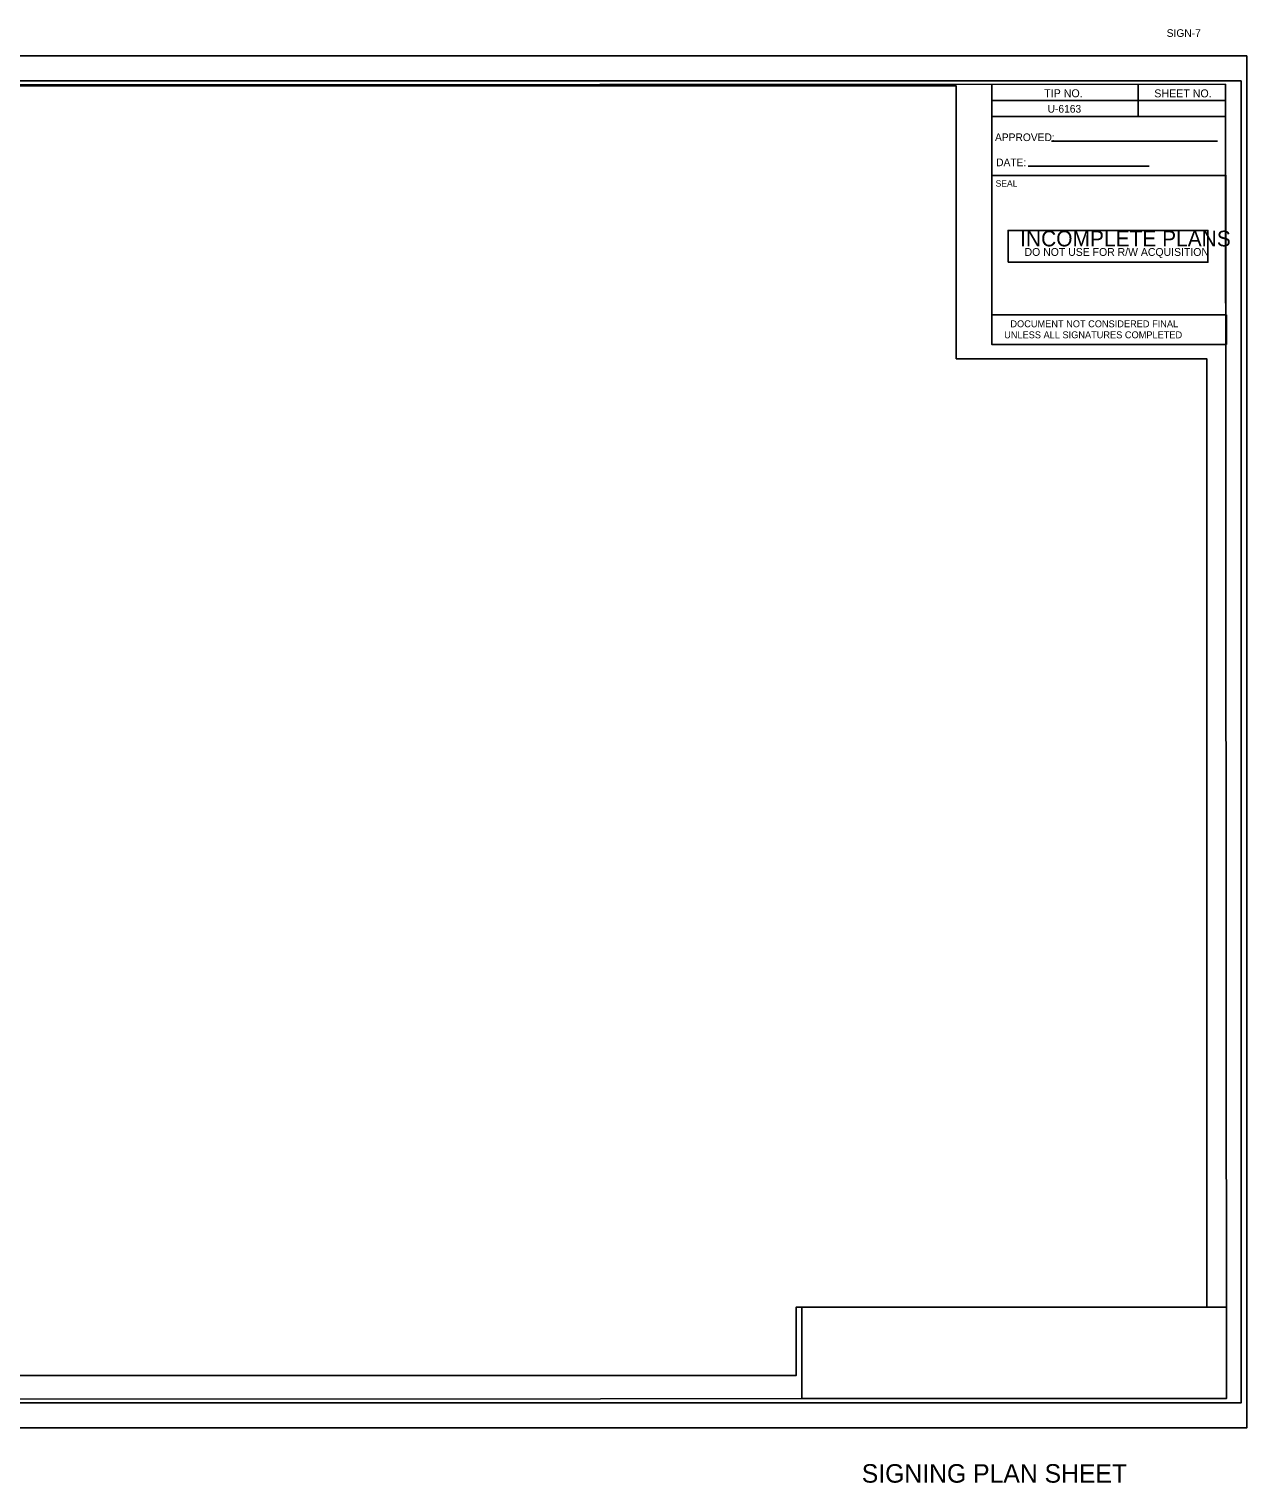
# Model space of a CAD drawing. Extents: x 1721764 to 1725755, y 971408 to 972569.
# Drawn here: x 1722736 to 1723709, y 971408 to 972569 of the extents above; entities that cross this region are included whole.
import ezdxf

# ---------------------------------------------------------------- set-up
doc = ezdxf.new("R2010")
doc.units = 0
for name, color, linetype in [('Default', 7, 'Continuous'), ('Matchline Text', 7, 'Continuous'), ('Prop Text', 7, 'Continuous'), ('Scratch_Level_3', 7, 'Continuous'), ('Sheet Block Title CELL', 7, 'Continuous'), ('Sheet Plan CELL', 7, 'Continuous'), ('Sheet Plan Layout CELL', 7, 'Continuous'), ('Sheet Plot Border Inside CELL', 7, 'Continuous'), ('Sheet Plot Border Outside CELL', 7, 'Continuous'), ('Sheet Sticker Exception Certification CELL', 7, 'Continuous'), ('Sheet Sticker Incomplete CELL', 7, 'Continuous')]:
    doc.layers.add(name, color=color, linetype=linetype)

msp = doc.modelspace()

# ---------------------------------------------------------------- linework, layer by layer
at = {"layer": 'Matchline Text'}
for p, q in [((1723621.7, 972499.7), (1723621.7, 972524.6)), ((1723691.9, 972524.6), (1723691.9, 972524.6)), ((1723691.9, 972524.6), (1723691.9, 972524.6)), ((1723691.9, 972524.6), (1723691.9, 972524.6)), ((1723691.9, 972524.6), (1723691.9, 972524.6)), ((1723691.9, 972524.6), (1723691.9, 972524.6)), ((1723691.9, 972524.6), (1723691.9, 972524.6)), ((1723691.9, 972524.6), (1723691.9, 972524.6)), ((1723691.9, 972524.6), (1723691.9, 972524.6)), ((1723533.9, 972459.9), (1723630.7, 972459.9))]:
    msp.add_line(p, q, dxfattribs=at)
at = {"layer": 'Prop Text'}
msp.add_line((1723552.6, 972479.8), (1723685.2, 972479.8), dxfattribs=at)
at = {"layer": 'Scratch_Level_3'}
msp.add_lwpolyline([(1722196.6, 972524), (1723476.5, 972524), (1723476.5, 972306.2), (1723676.6, 972306.2), (1723676.6, 971548.6), (1723348.6, 971548.6), (1723348.6, 971494), (1722196.6, 971494)], close=True, dxfattribs=at)
at = {"layer": 'Sheet Block Title CELL'}
msp.add_lwpolyline([(1723353.2, 971475.7), (1723692.3, 971475.7), (1723692.3, 971548.6), (1723353.2, 971548.6)], close=True, dxfattribs=at)
at = {"layer": 'Sheet Plan CELL'}
for p, q in [((1723708.7, 972548), (1723708.7, 972548)), ((1723704.2, 972528), (1723704.2, 972528))]:
    msp.add_line(p, q, dxfattribs=at)
at = {"layer": 'Sheet Plan Layout CELL'}
for p, q in [((1723504.9, 972499.7), (1723504.9, 972524.6)), ((1723621.7, 972499.7), (1723621.7, 972524.6)), ((1723504.9, 972512.4), (1723621.7, 972512.4)), ((1723621.7, 972512.4), (1723691.9, 972512.4)), ((1723504.9, 972499.7), (1723691.9, 972499.7)), ((1723504.9, 972452.5), (1723504.9, 972499.7))]:
    msp.add_line(p, q, dxfattribs=at)
for points in [[(1723691.7, 972525.5), (1722192, 972524.7), (1722192.6, 971474.9), (1723692.3, 971475.7)], [(1723504.9, 972452.5), (1723691.9, 972452.5), (1723691.9, 972341.1), (1723504.9, 972341.1)]]:
    msp.add_lwpolyline(points, close=True, dxfattribs=at)
at = {"layer": 'Sheet Plot Border Inside CELL'}
msp.add_lwpolyline([(1723704.2, 972528), (1722039.1, 972528), (1722039.1, 971472.3), (1723704.2, 971472.3)], close=True, dxfattribs=at)
at = {"layer": 'Sheet Plot Border Outside CELL'}
msp.add_lwpolyline([(1723708.7, 972548), (1722026.1, 972548), (1722026.1, 971452.3), (1723708.7, 971452.3)], close=True, dxfattribs=at)
at = {"layer": 'Sheet Sticker Exception Certification CELL'}
msp.add_lwpolyline([(1723504.9, 972341.1), (1723692.3, 972341.1), (1723692.3, 972317.6), (1723504.9, 972317.6)], close=True, dxfattribs=at)
at = {"layer": 'Sheet Sticker Incomplete CELL'}
msp.add_lwpolyline([(1723517.9, 972383.2), (1723517.9, 972408.7), (1723677.5, 972408.7), (1723677.5, 972383.2)], close=True, dxfattribs=at)

# ---------------------------------------------------------------- texts
at = {"layer": 'Default'}
msp.add_text('SIGNING PLAN SHEET', height=14.773, dxfattribs=at).set_placement((1723401.1, 971408.5))
at = {"layer": 'Prop Text'}
for s, height, p in [('SIGN-7', 6.11, (1723644.6, 972563.2)), ('TIP NO.', 6.36, (1723546.8, 972515)), ('SHEET NO.', 6.36, (1723634.7, 972514.9)), ('U-6163', 6.11, (1723549.5, 972502.7)), ('APPROVED:', 6.11, (1723507.5, 972480)), ('DATE:', 6.11, (1723508.4, 972459.9)), ('SEAL', 5.09, (1723508, 972443.6))]:
    msp.add_text(s, height=height, rotation=359.9949, dxfattribs=at).set_placement(p)
at = {"layer": 'Sheet Sticker Exception Certification CELL'}
for s, p in [('DOCUMENT NOT CONSIDERED FINAL', (1723519.8, 972331.3)), ('UNLESS ALL SIGNATURES COMPLETED', (1723514.8, 972322.5))]:
    msp.add_text(s, height=5.498, dxfattribs=at).set_placement(p)
at = {"layer": 'Sheet Sticker Incomplete CELL'}
for s, height, p in [('INCOMPLETE PLANS', 12.506, (1723527.6, 972395.9)), ('DO NOT USE FOR R/W ACQUISITION', 6.253, (1723531.1, 972388.3))]:
    msp.add_text(s, height=height, dxfattribs=at).set_placement(p)

doc.saveas('drawing.dxf')
